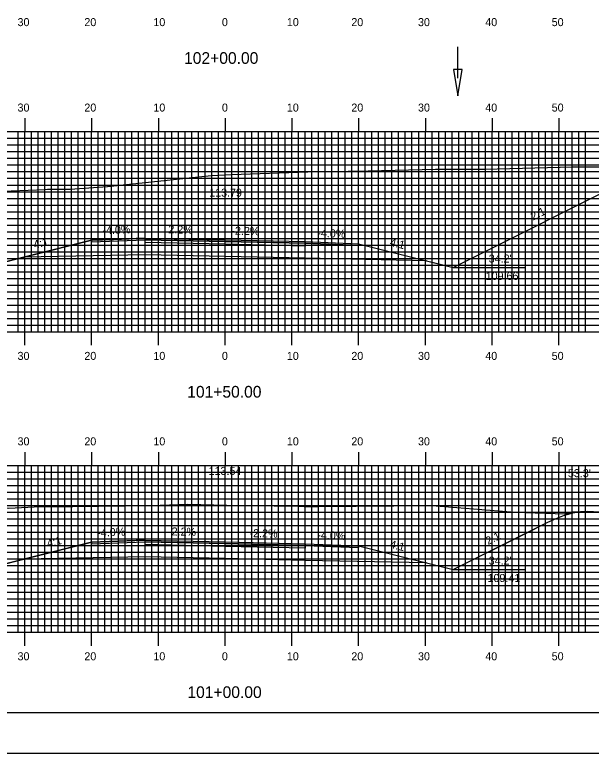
# Model space of a CAD drawing. Extents: x 1766907 to 1767250, y 442591 to 442811.
# Drawn here: x 1767040.9 to 1767127.3, y 442590.5 to 442701.2 of the extents above; entities that cross this region are included whole.
import ezdxf

# ---------------------------------------------------------------- set-up
doc = ezdxf.new("R2010")
doc.units = 0
for name, color, linetype in [('ANNOTATION', 7, 'Continuous'), ('BORDER', 7, 'Continuous'), ('D_Drainage_Ditch_Line', 7, 'Continuous'), ('D_Roadway_Centerline', 7, 'Continuous'), ('D_Roadway_Centerline_Text', 7, 'Continuous'), ('D_Roadway_Edge_Shoulder', 7, 'Continuous'), ('D_Roadway_Edge_TW', 7, 'Continuous'), ('D_Roadway_Pavement', 7, 'Continuous'), ('D_Roadway_SlopeLines', 7, 'Continuous'), ('D_Roadway_SubGrade', 7, 'Continuous'), ('D_Text_Standard', 7, 'Continuous'), ('H_V ANNOTATION', 7, 'Continuous'), ('MAJOR', 7, 'Continuous'), ('MINOR', 7, 'Continuous'), ('PDRAIN', 7, 'Continuous'), ('PLOT BOUNDARY', 7, 'Continuous'), ('S_Roadway_Centerline', 7, 'Continuous')]:
    doc.layers.add(name, color=color, linetype=linetype)

msp = doc.modelspace()

# ---------------------------------------------------------------- linework, layer by layer
at = {"layer": 'BORDER'}
msp.add_lwpolyline([(1766922.82, 442596.67), (1767242.82, 442596.67), (1767242.82, 442806.67), (1766922.82, 442806.67)], close=True, dxfattribs=at)
at = {"layer": 'D_Drainage_Ditch_Line'}
msp.add_line((1767107.29, 442691.66), (1767107.29, 442696.36), dxfattribs=at)
msp.add_lwpolyline([(1767107.94, 442692.97), (1767106.63, 442692.97), (1767107.29, 442689.03)], close=True, dxfattribs=at)
at = {"layer": 'D_Roadway_Centerline'}
for points in [[(1767010.43, 442676.47), (1767011.68, 442676.41), (1767012.93, 442676.19), (1767014.18, 442675.81), (1767015.43, 442675.26), (1767030.74, 442667.61), (1767038.25, 442663.86), (1767042.25, 442664.86), (1767052.42, 442667.4), (1767055.72, 442667.53), (1767060.42, 442667.72), (1767066.98, 442667.58), (1767072.42, 442667.46), (1767084.42, 442667.19), (1767092.42, 442666.87), (1767097.61, 442665.57), (1767102.6, 442664.33), (1767103.64, 442664.07), (1767106.6, 442663.33), (1767134.22, 442677.14)], [(1767038.25, 442618.61), (1767042.25, 442619.61), (1767042.25, 442619.61), (1767042.25, 442619.61), (1767052.42, 442622.15), (1767058.88, 442622.41), (1767060.42, 442622.47), (1767072.42, 442622.21), (1767076.62, 442622.11), (1767084.42, 442621.94), (1767092.42, 442621.62), (1767102.59, 442619.08), (1767102.6, 442619.08), (1767106.6, 442618.08), (1767106.6, 442618.08), (1767117.41, 442623.48), (1767120.75, 442625.15), (1767122, 442625.72), (1767123.25, 442626.19), (1767123.87, 442626.36), (1767124.5, 442626.54), (1767125.75, 442626.78)]]:
    msp.add_lwpolyline(points, dxfattribs=at)
at = {"layer": 'D_Roadway_Edge_Shoulder'}
for points in [[(1767060.42, 442667.72), (1767052.42, 442667.4), (1767052.42, 442667.15), (1767060.42, 442667.47)], [(1767084.42, 442667.19), (1767092.42, 442666.87), (1767092.42, 442666.62), (1767084.42, 442666.94)], [(1767060.42, 442622.47), (1767052.42, 442622.15), (1767052.42, 442621.9), (1767060.42, 442622.22)], [(1767084.42, 442621.94), (1767092.42, 442621.62), (1767092.42, 442621.37), (1767084.42, 442621.69)]]:
    msp.add_lwpolyline(points, close=True, dxfattribs=at)
at = {"layer": 'D_Roadway_Edge_TW'}
for points in [[(1767060.42, 442667.47), (1767060.42, 442667.72), (1767072.42, 442667.46), (1767084.42, 442667.19), (1767084.42, 442666.94), (1767072.42, 442667.21)], [(1767060.42, 442622.22), (1767060.42, 442622.47), (1767072.42, 442622.21), (1767084.42, 442621.94), (1767084.42, 442621.69), (1767072.42, 442621.96)]]:
    msp.add_lwpolyline(points, close=True, dxfattribs=at)
at = {"layer": 'D_Roadway_Pavement'}
for points in [[(1767060.42, 442667.05), (1767060.42, 442667.47), (1767072.42, 442667.21), (1767084.42, 442666.94), (1767084.42, 442666.53), (1767072.42, 442666.79)], [(1767060.42, 442621.8), (1767060.42, 442622.22), (1767072.42, 442621.96), (1767084.42, 442621.69), (1767084.42, 442621.28), (1767072.42, 442621.54)]]:
    msp.add_lwpolyline(points, close=True, dxfattribs=at)
at = {"layer": 'D_Roadway_SlopeLines'}
for points in [[(1767106.6, 442663.33), (1767134.22, 442677.14), (1767135.48, 442677.68), (1767136.72, 442678.06), (1767137.98, 442678.27), (1767139.22, 442678.32)], [(1767052.42, 442667.4), (1767038.25, 442663.86)], [(1767092.42, 442666.87), (1767106.6, 442663.33)], [(1767106.6, 442618.08), (1767120.75, 442625.15), (1767122, 442625.72), (1767123.25, 442626.19), (1767124.5, 442626.54), (1767125.75, 442626.78)], [(1767052.42, 442622.15), (1767038.25, 442618.61)], [(1767092.42, 442621.62), (1767106.6, 442618.08)]]:
    msp.add_lwpolyline(points, dxfattribs=at)
at = {"layer": 'D_Roadway_SubGrade'}
for points in [[(1767060.42, 442665.22), (1767042.25, 442664.86), (1767052.42, 442667.4), (1767052.42, 442667.15), (1767060.42, 442667.47), (1767072.42, 442667.21), (1767084.42, 442666.94), (1767092.42, 442666.62), (1767092.42, 442666.87), (1767102.6, 442664.33), (1767084.42, 442664.69), (1767072.42, 442664.96)], [(1767060.42, 442619.97), (1767042.25, 442619.61), (1767052.42, 442622.15), (1767052.42, 442621.9), (1767060.42, 442622.22), (1767072.42, 442621.96), (1767084.42, 442621.69), (1767092.42, 442621.37), (1767092.42, 442621.62), (1767102.6, 442619.08), (1767084.42, 442619.44), (1767072.42, 442619.71)]]:
    msp.add_lwpolyline(points, close=True, dxfattribs=at)
at = {"layer": 'MAJOR'}
for p, q in [((1767042.42, 442685.67), (1767042.42, 442683.67)), ((1767052.42, 442685.67), (1767052.42, 442683.67)), ((1767062.42, 442685.67), (1767062.42, 442683.67)), ((1767072.42, 442685.67), (1767072.42, 442683.67)), ((1767082.42, 442685.67), (1767082.42, 442683.67)), ((1767092.42, 442685.67), (1767092.42, 442683.67)), ((1767102.42, 442685.67), (1767102.42, 442683.67)), ((1767112.42, 442685.67), (1767112.42, 442683.67)), ((1767122.42, 442685.67), (1767122.42, 442683.67)), ((1766932.42, 442683.67), (1767212.42, 442683.67)), ((1766932.42, 442683.67), (1767212.42, 442683.67)), ((1767042.42, 442653.67), (1767042.42, 442683.67)), ((1767052.42, 442653.67), (1767052.42, 442683.67)), ((1767062.42, 442653.67), (1767062.42, 442683.67)), ((1767072.42, 442653.67), (1767072.42, 442683.67)), ((1767082.42, 442653.67), (1767082.42, 442683.67)), ((1767092.42, 442653.67), (1767092.42, 442683.67)), ((1767102.42, 442653.67), (1767102.42, 442683.67)), ((1767112.42, 442653.67), (1767112.42, 442683.67)), ((1767122.42, 442653.67), (1767122.42, 442683.67)), ((1766932.42, 442678.67), (1767212.42, 442678.67)), ((1766932.42, 442673.67), (1767212.42, 442673.67)), ((1766932.42, 442668.67), (1767212.42, 442668.67)), ((1766932.42, 442663.67), (1767212.42, 442663.67)), ((1766932.42, 442658.67), (1767212.42, 442658.67)), ((1766932.42, 442653.67), (1767212.42, 442653.67)), ((1766932.42, 442653.67), (1767212.42, 442653.67)), ((1767042.42, 442651.66), (1767042.42, 442653.67)), ((1767052.42, 442651.66), (1767052.42, 442653.67)), ((1767062.42, 442651.66), (1767062.42, 442653.67)), ((1767072.42, 442651.66), (1767072.42, 442653.67)), ((1767082.42, 442651.66), (1767082.42, 442653.67)), ((1767092.42, 442651.66), (1767092.42, 442653.67)), ((1767102.42, 442651.66), (1767102.42, 442653.67)), ((1767112.42, 442651.66), (1767112.42, 442653.67)), ((1767122.42, 442651.66), (1767122.42, 442653.67)), ((1767042.42, 442635.67), (1767042.42, 442633.67)), ((1767052.42, 442635.67), (1767052.42, 442633.67)), ((1767062.42, 442635.67), (1767062.42, 442633.67)), ((1767072.42, 442635.67), (1767072.42, 442633.67)), ((1767082.42, 442635.67), (1767082.42, 442633.67)), ((1767092.42, 442635.67), (1767092.42, 442633.67)), ((1767102.42, 442635.67), (1767102.42, 442633.67)), ((1767112.42, 442635.67), (1767112.42, 442633.67)), ((1767122.42, 442635.67), (1767122.42, 442633.67)), ((1766932.42, 442633.67), (1767212.42, 442633.67)), ((1766932.42, 442633.67), (1767212.42, 442633.67)), ((1767042.42, 442608.67), (1767042.42, 442633.67)), ((1767052.42, 442608.67), (1767052.42, 442633.67)), ((1767062.42, 442608.67), (1767062.42, 442633.67)), ((1767072.42, 442608.67), (1767072.42, 442633.67)), ((1767082.42, 442608.67), (1767082.42, 442633.67)), ((1767092.42, 442608.67), (1767092.42, 442633.67)), ((1767102.42, 442608.67), (1767102.42, 442633.67)), ((1767112.42, 442608.67), (1767112.42, 442633.67)), ((1767122.42, 442608.67), (1767122.42, 442633.67)), ((1766932.42, 442628.67), (1767212.42, 442628.67)), ((1766932.42, 442623.67), (1767212.42, 442623.67)), ((1766932.42, 442618.67), (1767212.42, 442618.67)), ((1766932.42, 442613.67), (1767212.42, 442613.67)), ((1766932.42, 442608.67), (1767212.42, 442608.67)), ((1766932.42, 442608.67), (1767212.42, 442608.67)), ((1767042.42, 442606.66), (1767042.42, 442608.67)), ((1767052.42, 442606.66), (1767052.42, 442608.67)), ((1767062.42, 442606.66), (1767062.42, 442608.67)), ((1767072.42, 442606.66), (1767072.42, 442608.67)), ((1767082.42, 442606.66), (1767082.42, 442608.67)), ((1767092.42, 442606.66), (1767092.42, 442608.67)), ((1767102.42, 442606.66), (1767102.42, 442608.67)), ((1767112.42, 442606.66), (1767112.42, 442608.67)), ((1767122.42, 442606.66), (1767122.42, 442608.67))]:
    msp.add_line(p, q, dxfattribs=at)
at = {"layer": 'MINOR'}
for p, q in [((1767041.42, 442653.67), (1767041.42, 442683.67)), ((1767043.42, 442653.67), (1767043.42, 442683.67)), ((1767044.42, 442653.67), (1767044.42, 442683.67)), ((1767045.42, 442653.67), (1767045.42, 442683.67)), ((1767046.42, 442653.67), (1767046.42, 442683.67)), ((1767047.42, 442653.67), (1767047.42, 442683.67)), ((1767048.42, 442653.67), (1767048.42, 442683.67)), ((1767049.42, 442653.67), (1767049.42, 442683.67)), ((1767050.42, 442653.67), (1767050.42, 442683.67)), ((1767051.42, 442653.67), (1767051.42, 442683.67)), ((1767053.42, 442653.67), (1767053.42, 442683.67)), ((1767054.42, 442653.67), (1767054.42, 442683.67)), ((1767055.42, 442653.67), (1767055.42, 442683.67)), ((1767056.42, 442653.67), (1767056.42, 442683.67)), ((1767057.42, 442653.67), (1767057.42, 442683.67)), ((1767058.42, 442653.67), (1767058.42, 442683.67)), ((1767059.42, 442653.67), (1767059.42, 442683.67)), ((1767060.42, 442653.67), (1767060.42, 442683.67)), ((1767061.42, 442653.67), (1767061.42, 442683.67)), ((1767063.42, 442653.67), (1767063.42, 442683.67)), ((1767064.42, 442653.67), (1767064.42, 442683.67)), ((1767065.42, 442653.67), (1767065.42, 442683.67)), ((1767066.42, 442653.67), (1767066.42, 442683.67)), ((1767067.42, 442653.67), (1767067.42, 442683.67)), ((1767068.42, 442653.67), (1767068.42, 442683.67)), ((1767069.42, 442653.67), (1767069.42, 442683.67)), ((1767070.42, 442653.67), (1767070.42, 442683.67)), ((1767071.42, 442653.67), (1767071.42, 442683.67)), ((1767073.42, 442653.67), (1767073.42, 442683.67)), ((1767074.42, 442653.67), (1767074.42, 442683.67)), ((1767075.42, 442653.67), (1767075.42, 442683.67)), ((1767076.42, 442653.67), (1767076.42, 442683.67)), ((1767077.42, 442653.67), (1767077.42, 442683.67)), ((1767078.42, 442653.67), (1767078.42, 442683.67)), ((1767079.42, 442653.67), (1767079.42, 442683.67)), ((1767080.42, 442653.67), (1767080.42, 442683.67)), ((1767081.42, 442653.67), (1767081.42, 442683.67)), ((1767083.42, 442653.67), (1767083.42, 442683.67)), ((1767084.42, 442653.67), (1767084.42, 442683.67)), ((1767085.42, 442653.67), (1767085.42, 442683.67)), ((1767086.42, 442653.67), (1767086.42, 442683.67)), ((1767087.42, 442653.67), (1767087.42, 442683.67)), ((1767088.42, 442653.67), (1767088.42, 442683.67)), ((1767089.42, 442653.67), (1767089.42, 442683.67)), ((1767090.42, 442653.67), (1767090.42, 442683.67)), ((1767091.42, 442653.67), (1767091.42, 442683.67)), ((1767093.42, 442653.67), (1767093.42, 442683.67)), ((1767094.42, 442653.67), (1767094.42, 442683.67)), ((1767095.42, 442653.67), (1767095.42, 442683.67)), ((1767096.42, 442653.67), (1767096.42, 442683.67)), ((1767097.42, 442653.67), (1767097.42, 442683.67)), ((1767098.42, 442653.67), (1767098.42, 442683.67)), ((1767099.42, 442653.67), (1767099.42, 442683.67)), ((1767100.42, 442653.67), (1767100.42, 442683.67)), ((1767101.42, 442653.67), (1767101.42, 442683.67)), ((1767103.42, 442653.67), (1767103.42, 442683.67)), ((1767104.42, 442653.67), (1767104.42, 442683.67)), ((1767105.42, 442653.67), (1767105.42, 442683.67)), ((1767106.42, 442653.67), (1767106.42, 442683.67)), ((1767107.42, 442653.67), (1767107.42, 442683.67)), ((1767108.42, 442653.67), (1767108.42, 442683.67)), ((1767109.42, 442653.67), (1767109.42, 442683.67)), ((1767110.42, 442653.67), (1767110.42, 442683.67)), ((1767111.42, 442653.67), (1767111.42, 442683.67)), ((1767113.42, 442653.67), (1767113.42, 442683.67)), ((1767114.42, 442653.67), (1767114.42, 442683.67)), ((1767115.42, 442653.67), (1767115.42, 442683.67)), ((1767116.42, 442653.67), (1767116.42, 442683.67)), ((1767117.42, 442653.67), (1767117.42, 442683.67)), ((1767118.42, 442653.67), (1767118.42, 442683.67)), ((1767119.42, 442653.67), (1767119.42, 442683.67)), ((1767120.42, 442653.67), (1767120.42, 442683.67)), ((1767121.42, 442653.67), (1767121.42, 442683.67)), ((1767123.42, 442653.67), (1767123.42, 442683.67)), ((1767124.42, 442653.67), (1767124.42, 442683.67)), ((1767125.42, 442653.67), (1767125.42, 442683.67)), ((1767126.42, 442653.67), (1767126.42, 442683.67)), ((1766932.42, 442682.67), (1767212.42, 442682.67)), ((1766932.42, 442681.67), (1767212.42, 442681.67)), ((1766932.42, 442680.67), (1767212.42, 442680.67)), ((1766932.42, 442679.67), (1767212.42, 442679.67)), ((1766932.42, 442677.67), (1767212.42, 442677.67)), ((1766932.42, 442676.67), (1767212.42, 442676.67)), ((1766932.42, 442675.67), (1767212.42, 442675.67)), ((1766932.42, 442674.67), (1767212.42, 442674.67)), ((1766932.42, 442672.67), (1767212.42, 442672.67)), ((1766932.42, 442671.67), (1767212.42, 442671.67)), ((1766932.42, 442670.67), (1767212.42, 442670.67)), ((1766932.42, 442669.67), (1767212.42, 442669.67)), ((1766932.42, 442667.67), (1767212.42, 442667.67)), ((1766932.42, 442666.67), (1767212.42, 442666.67)), ((1766932.42, 442665.67), (1767212.42, 442665.67)), ((1766932.42, 442664.67), (1767212.42, 442664.67)), ((1766932.42, 442662.67), (1767212.42, 442662.67)), ((1766932.42, 442661.67), (1767212.42, 442661.67)), ((1766932.42, 442660.67), (1767212.42, 442660.67)), ((1766932.42, 442659.67), (1767212.42, 442659.67)), ((1766932.42, 442657.67), (1767212.42, 442657.67)), ((1766932.42, 442656.67), (1767212.42, 442656.67)), ((1766932.42, 442655.67), (1767212.42, 442655.67)), ((1766932.42, 442654.67), (1767212.42, 442654.67)), ((1767041.42, 442608.67), (1767041.42, 442633.67)), ((1767043.42, 442608.67), (1767043.42, 442633.67)), ((1767044.42, 442608.67), (1767044.42, 442633.67)), ((1767045.42, 442608.67), (1767045.42, 442633.67)), ((1767046.42, 442608.67), (1767046.42, 442633.67)), ((1767047.42, 442608.67), (1767047.42, 442633.67)), ((1767048.42, 442608.67), (1767048.42, 442633.67)), ((1767049.42, 442608.67), (1767049.42, 442633.67)), ((1767050.42, 442608.67), (1767050.42, 442633.67)), ((1767051.42, 442608.67), (1767051.42, 442633.67)), ((1767053.42, 442608.67), (1767053.42, 442633.67)), ((1767054.42, 442608.67), (1767054.42, 442633.67)), ((1767055.42, 442608.67), (1767055.42, 442633.67)), ((1767056.42, 442608.67), (1767056.42, 442633.67)), ((1767057.42, 442608.67), (1767057.42, 442633.67)), ((1767058.42, 442608.67), (1767058.42, 442633.67)), ((1767059.42, 442608.67), (1767059.42, 442633.67)), ((1767060.42, 442608.67), (1767060.42, 442633.67)), ((1767061.42, 442608.67), (1767061.42, 442633.67)), ((1767063.42, 442608.67), (1767063.42, 442633.67)), ((1767064.42, 442608.67), (1767064.42, 442633.67)), ((1767065.42, 442608.67), (1767065.42, 442633.67)), ((1767066.42, 442608.67), (1767066.42, 442633.67)), ((1767067.42, 442608.67), (1767067.42, 442633.67)), ((1767068.42, 442608.67), (1767068.42, 442633.67)), ((1767069.42, 442608.67), (1767069.42, 442633.67)), ((1767070.42, 442608.67), (1767070.42, 442633.67)), ((1767071.42, 442608.67), (1767071.42, 442633.67)), ((1767073.42, 442608.67), (1767073.42, 442633.67)), ((1767074.42, 442608.67), (1767074.42, 442633.67)), ((1767075.42, 442608.67), (1767075.42, 442633.67)), ((1767076.42, 442608.67), (1767076.42, 442633.67)), ((1767077.42, 442608.67), (1767077.42, 442633.67)), ((1767078.42, 442608.67), (1767078.42, 442633.67)), ((1767079.42, 442608.67), (1767079.42, 442633.67)), ((1767080.42, 442608.67), (1767080.42, 442633.67)), ((1767081.42, 442608.67), (1767081.42, 442633.67)), ((1767083.42, 442608.67), (1767083.42, 442633.67)), ((1767084.42, 442608.67), (1767084.42, 442633.67)), ((1767085.42, 442608.67), (1767085.42, 442633.67)), ((1767086.42, 442608.67), (1767086.42, 442633.67)), ((1767087.42, 442608.67), (1767087.42, 442633.67)), ((1767088.42, 442608.67), (1767088.42, 442633.67)), ((1767089.42, 442608.67), (1767089.42, 442633.67)), ((1767090.42, 442608.67), (1767090.42, 442633.67)), ((1767091.42, 442608.67), (1767091.42, 442633.67)), ((1767093.42, 442608.67), (1767093.42, 442633.67)), ((1767094.42, 442608.67), (1767094.42, 442633.67)), ((1767095.42, 442608.67), (1767095.42, 442633.67)), ((1767096.42, 442608.67), (1767096.42, 442633.67)), ((1767097.42, 442608.67), (1767097.42, 442633.67)), ((1767098.42, 442608.67), (1767098.42, 442633.67)), ((1767099.42, 442608.67), (1767099.42, 442633.67)), ((1767100.42, 442608.67), (1767100.42, 442633.67)), ((1767101.42, 442608.67), (1767101.42, 442633.67)), ((1767103.42, 442608.67), (1767103.42, 442633.67)), ((1767104.42, 442608.67), (1767104.42, 442633.67)), ((1767105.42, 442608.67), (1767105.42, 442633.67)), ((1767106.42, 442608.67), (1767106.42, 442633.67)), ((1767107.42, 442608.67), (1767107.42, 442633.67)), ((1767108.42, 442608.67), (1767108.42, 442633.67)), ((1767109.42, 442608.67), (1767109.42, 442633.67)), ((1767110.42, 442608.67), (1767110.42, 442633.67)), ((1767111.42, 442608.67), (1767111.42, 442633.67)), ((1767113.42, 442608.67), (1767113.42, 442633.67)), ((1767114.42, 442608.67), (1767114.42, 442633.67)), ((1767115.42, 442608.67), (1767115.42, 442633.67)), ((1767116.42, 442608.67), (1767116.42, 442633.67)), ((1767117.42, 442608.67), (1767117.42, 442633.67)), ((1767118.42, 442608.67), (1767118.42, 442633.67)), ((1767119.42, 442608.67), (1767119.42, 442633.67)), ((1767120.42, 442608.67), (1767120.42, 442633.67)), ((1767121.42, 442608.67), (1767121.42, 442633.67)), ((1767123.42, 442608.67), (1767123.42, 442633.67)), ((1767124.42, 442608.67), (1767124.42, 442633.67)), ((1767125.42, 442608.67), (1767125.42, 442633.67)), ((1767126.42, 442608.67), (1767126.42, 442633.67)), ((1766932.42, 442632.67), (1767212.42, 442632.67)), ((1766932.42, 442631.67), (1767212.42, 442631.67)), ((1766932.42, 442630.67), (1767212.42, 442630.67)), ((1766932.42, 442629.67), (1767212.42, 442629.67)), ((1766932.42, 442627.67), (1767212.42, 442627.67)), ((1766932.42, 442626.67), (1767212.42, 442626.67)), ((1766932.42, 442625.67), (1767212.42, 442625.67)), ((1766932.42, 442624.67), (1767212.42, 442624.67)), ((1766932.42, 442622.67), (1767212.42, 442622.67)), ((1766932.42, 442621.67), (1767212.42, 442621.67)), ((1766932.42, 442620.67), (1767212.42, 442620.67)), ((1766932.42, 442619.67), (1767212.42, 442619.67)), ((1766932.42, 442617.67), (1767212.42, 442617.67)), ((1766932.42, 442616.67), (1767212.42, 442616.67)), ((1766932.42, 442615.67), (1767212.42, 442615.67)), ((1766932.42, 442614.67), (1767212.42, 442614.67)), ((1766932.42, 442612.67), (1767212.42, 442612.67)), ((1766932.42, 442611.67), (1767212.42, 442611.67)), ((1766932.42, 442610.67), (1767212.42, 442610.67)), ((1766932.42, 442609.67), (1767212.42, 442609.67))]:
    msp.add_line(p, q, dxfattribs=at)
at = {"layer": 'PDRAIN'}
for p, q in [((1767106.6, 442663.33), (1767117.37, 442663.33)), ((1767106.6, 442618.08), (1767117.37, 442618.08))]:
    msp.add_line(p, q, dxfattribs=at)
at = {"layer": 'PLOT BOUNDARY'}
msp.add_lwpolyline([(1766906.64, 442590.55), (1767246.64, 442590.55), (1767246.64, 442810.55), (1766906.64, 442810.55)], close=True, dxfattribs=at)
at = {"layer": 'S_Roadway_Centerline'}
for points in [[(1767037.76, 442674.71), (1767045.46, 442675.01), (1767045.83, 442675.05), (1767049.18, 442675.07), (1767054.8, 442675.46), (1767070.35, 442677.09), (1767073.4, 442677.26), (1767084.82, 442677.65), (1767093.86, 442677.81), (1767103.93, 442678.04), (1767108.26, 442678.04), (1767111.27, 442678.02), (1767124.53, 442678.38), (1767131.45, 442678.41)], [(1766989.71, 442626.71), (1767024.47, 442627.74), (1767028.1, 442627.66), (1767034.54, 442627.6), (1767035.3, 442627.48), (1767038.13, 442627.55), (1767039.99, 442627.27), (1767044.74, 442627.52), (1767045.77, 442627.51), (1767047.42, 442627.52), (1767049.61, 442627.53), (1767061.3, 442627.65), (1767066.81, 442627.87), (1767072.68, 442627.72), (1767083.3, 442627.55), (1767084.25, 442627.5), (1767084.84, 442627.5), (1767086.38, 442627.51), (1767103.39, 442627.66), (1767115.87, 442626.68), (1767123.36, 442626.4), (1767124.52, 442626.73), (1767126.76, 442626.82), (1767129.37, 442626.65)]]:
    msp.add_lwpolyline(points, dxfattribs=at)

# ---------------------------------------------------------------- texts
at = {"layer": 'ANNOTATION'}
for s, rotation, p in [('2:1', 26.5655, (1767118.56, 442670.34)), ('-4.0%', 2.2906, (1767054.06, 442668.27)), ('2.2%', 358.7397, (1767063.9, 442668.44)), ('-2.2%', 358.7397, (1767073.35, 442668.24)), ('-4.0%', 357.7096, (1767086.22, 442667.92)), ('4:1', 14.0386, (1767043.87, 442666.12)), ('4:1', 345.9597, (1767097.02, 442666.59)), ('-4.0%', 2.2907, (1767053.28, 442622.99)), ('2.2%', 358.7397, (1767064.39, 442623.18)), ('-2.2%', 358.7397, (1767076.07, 442622.93)), ('-4.0%', 357.7093, (1767086.22, 442622.67)), ('4:1', 14.0395, (1767045.87, 442621.37)), ('2:1', 26.566, (1767111.82, 442621.72)), ('4:1', 345.9616, (1767097.01, 442621.34))]:
    msp.add_text(s, height=1.2, rotation=rotation, dxfattribs=at).set_placement(p)
for s, p in [("34.2'", (1767111.91, 442664.05)), ('109.66', (1767111.46, 442661.45)), ("34.2'", (1767111.91, 442618.8)), ('109.41', (1767111.74, 442616.2))]:
    msp.add_text(s, height=1.2, dxfattribs=at).set_placement(p)
at = {"layer": 'D_Roadway_Centerline'}
for s, p in [('C', (1767072.42, 442667.46)), ('L', (1767072.42, 442667.45)), ('C', (1767072.42, 442622.21)), ('L', (1767072.42, 442622.2))]:
    msp.add_text(s, height=0.0146, dxfattribs=at).set_placement(p)
at = {"layer": 'D_Roadway_Centerline_Text'}
for s, p in [('113.79', (1767070.03, 442673.92)), ('113.54', (1767069.95, 442632.24))]:
    msp.add_text(s, height=1.2, dxfattribs=at).set_placement(p)
at = {"layer": 'D_Text_Standard'}
msp.add_text("53.3'", height=1.2, dxfattribs=at).set_placement((1767123.78, 442631.9))
at = {"layer": 'H_V ANNOTATION'}
for s, height, p in [('30', 1.2, (1767041.32, 442699.47)), ('20', 1.2, (1767051.33, 442699.47)), ('10', 1.2, (1767061.67, 442699.47)), ('0', 1.2, (1767071.94, 442699.47)), ('10', 1.2, (1767081.67, 442699.47)), ('20', 1.2, (1767091.33, 442699.47)), ('30', 1.2, (1767101.32, 442699.47)), ('40', 1.2, (1767111.4, 442699.47)), ('50', 1.2, (1767121.35, 442699.47)), ('102+00.00', 1.75, (1767066.27, 442693.82)), ('30', 1.2, (1767041.32, 442686.67)), ('20', 1.2, (1767051.33, 442686.67)), ('10', 1.2, (1767061.67, 442686.67)), ('0', 1.2, (1767071.94, 442686.67)), ('10', 1.2, (1767081.67, 442686.67)), ('20', 1.2, (1767091.33, 442686.67)), ('30', 1.2, (1767101.32, 442686.67)), ('40', 1.2, (1767111.4, 442686.67)), ('50', 1.2, (1767121.35, 442686.67)), ('30', 1.2, (1767041.32, 442649.47)), ('20', 1.2, (1767051.33, 442649.47)), ('10', 1.2, (1767061.67, 442649.47)), ('0', 1.2, (1767071.94, 442649.47)), ('10', 1.2, (1767081.67, 442649.47)), ('20', 1.2, (1767091.33, 442649.47)), ('30', 1.2, (1767101.32, 442649.47)), ('40', 1.2, (1767111.4, 442649.47)), ('50', 1.2, (1767121.35, 442649.47)), ('101+50.00', 1.75, (1767066.74, 442643.82)), ('30', 1.2, (1767041.32, 442636.67)), ('20', 1.2, (1767051.33, 442636.67)), ('10', 1.2, (1767061.67, 442636.67)), ('0', 1.2, (1767071.94, 442636.67)), ('10', 1.2, (1767081.67, 442636.67)), ('20', 1.2, (1767091.33, 442636.67)), ('30', 1.2, (1767101.32, 442636.67)), ('40', 1.2, (1767111.4, 442636.67)), ('50', 1.2, (1767121.35, 442636.67)), ('30', 1.2, (1767041.32, 442604.47)), ('20', 1.2, (1767051.33, 442604.47)), ('10', 1.2, (1767061.67, 442604.47)), ('0', 1.2, (1767071.94, 442604.47)), ('10', 1.2, (1767081.67, 442604.47)), ('20', 1.2, (1767091.33, 442604.47)), ('30', 1.2, (1767101.32, 442604.47)), ('40', 1.2, (1767111.4, 442604.47)), ('50', 1.2, (1767121.35, 442604.47)), ('101+00.00', 1.75, (1767066.77, 442598.82))]:
    msp.add_text(s, height=height, dxfattribs=at).set_placement(p)

doc.saveas('drawing.dxf')
